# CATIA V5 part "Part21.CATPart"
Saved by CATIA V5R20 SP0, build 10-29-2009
Part number: 9SA200018-T
Revision: ANY
Definition: UNKNOWN
Nomenclature: 9SA200018-T
Source: Unknown
Bounding box of the stored display mesh (mm): x -7.312 to 7.312, y 0 to 5.95, z -7.5 to 7.5
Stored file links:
  C:\Users\Utente\Desktop\IO LAVORO\3D X SITO CF\CUMSA\3D files SA\SA 200018\Part21.CATPart
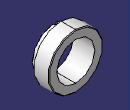
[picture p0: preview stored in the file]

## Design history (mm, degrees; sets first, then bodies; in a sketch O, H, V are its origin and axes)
Body1 "Chaflán1" (main body)
  Solid1: solid without history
